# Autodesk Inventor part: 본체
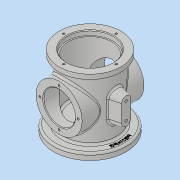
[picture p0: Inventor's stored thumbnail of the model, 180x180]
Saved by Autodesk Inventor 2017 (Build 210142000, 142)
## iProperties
Part Number: 본체
Material: 일반
Document SubType Name: Modeling
Designer: MRC
Density: 1 g/cm^3
Appearance: 기본값
Mass: 293.451 g
Surface Area: 769.493 cm^2
Volume: 293.451 cm^3
Author: MRC
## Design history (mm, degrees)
sketch "스케치1"
  geometry: C1 r 55 at (0, 0); 1 further point
  constraints: 1 centre point, 1 coincident
  dimensions: "d0" = 110 diameter of C1
extrude "돌출1" new body sketch "스케치1" distance "d1" = 10; taper "d2" = 0 deg
sketch "스케치2"
  geometry: C1 r 40 at (0, 0); 1 further point
  constraints: 1 centre point, 1 coincident
  dimensions: "d3" = 80 diameter of C1
extrude "돌출2" join sketch "스케치2" distance "d4" = 88; taper "d5" = 0 deg
sketch "스케치3"
  geometry: C1 r 47 at (0, 0); 1 further point
  constraints: 1 centre point, 1 coincident
  dimensions: "d6" = 94 diameter of C1
extrude "돌출3" join sketch "스케치3" distance "d7" = 10; taper "d8" = 0 deg
sketch "스케치4"
  geometry: L1 (-55, 0)-(55, 0) reference; C1 r 35 at (0, 54); 1 further point
  constraints: 1 centre point, 1 vertical alignment
  dimensions: "d9" = 70 diameter of C1; "d10" = 54 distance from line of L1 C1.centre
extrude "돌출4" join sketch "스케치4" stored distance "d11" = 94; taper "d12" = 0 deg
sketch "스케치5"
  geometry: C1 r 35 at (0, 0); 1 further point
  constraints: 1 centre point, 1 coincident
  dimensions: "d13" = 70 diameter of C1
extrude "돌출5" cut sketch "스케치5" distance "d14" = 7; taper "d15" = 0 deg
sketch "스케치6"
  geometry: C1 r 33 at (0, 0); 1 further point
  constraints: 1 centre point, 1 coincident
  dimensions: "d16" = 66 diameter of C1
extrude "돌출6" cut sketch "스케치6" distance "d17" = 79; taper "d18" = 0 deg
sketch "스케치7"
  geometry: C1 r 33 at (0, 0); 1 further point
  constraints: 1 centre point, 1 coincident
  dimensions: "d19" = 66 diameter of C1
extrude "돌출7" cut sketch "스케치7" distance "d20" = 16; taper "d21" = 0 deg
sketch "스케치8"
  geometry: C1 r 5 at (0, 0); 1 further point
  constraints: 1 centre point, 1 coincident
  dimensions: "d22" = 10 diameter of C1
extrude "돌출8" cut sketch "스케치8" distance "d23" = 16; taper "d24" = 0 deg
sketch "스케치9"
  geometry: C1 r 24 at (0, 0); 1 further point
  constraints: 1 centre point
  dimensions: "d25" = 48 diameter of C1
extrude "돌출9" cut sketch "스케치9" distance "d26" = 94; taper "d27" = 0 deg
sketch "스케치10"
  geometry: C1 r 24 at (0, 0) reference; C2 r 35 at (0, 0) reference; A1 r 29 centre (0, 0) between (0, 29) and (-29, 0); 3 further points
  constraints: 4 point on circle, 2 horizontal alignment, 2 vertical alignment, 1 centre point, 1 coincident
  dimensions: "d28" = 58 diameter of A1
hole "구멍1" sketch "스케치10" at (0, 29), (-29, 0), (29, 0), (0, -29) diameter "d29" = 3.242; stored, may be unused: countersink angle "d33" = 90 deg, drill point angle "d35" = 118 deg; dims "d30" = 6, "d31" = 4, "d32" = 2, "d34" = 8
sketch "스케치11"
  geometry: C1 r 35 at (0, 0) reference; C2 r 47 at (0, 0) reference; A1 r 40 centre (0, 0) between (0, 40) and (-40, 0); 3 further points
  constraints: 4 point on circle, 2 horizontal alignment, 2 vertical alignment, 1 centre point, 1 coincident
  dimensions: "d36" = 80 diameter of A1
hole "구멍2" sketch "스케치11" at (0, 40), (-40, 0), (0, -40), (40, 0) diameter "d37" = 3.242; stored, may be unused: countersink angle "d41" = 90 deg, drill point angle "d43" = 118 deg; dims "d38" = 6, "d39" = 4, "d40" = 2, "d42" = 8
node "작업 평면1"
sketch "스케치12"
  geometry: L1 (67, 0)-(41, 0); L2 (67, 7)-(41, 7); L3 (41, -7)-(67, -7); L4 (0, 55)-(0, -55) reference; A1 r 7 centre (67, 0) between (67, -7) and (67, 7); A2 r 7 centre (41, 0) between (41, 7) and (41, -7); 3 further points
  constraints: 8 end point, 4 point on circle, 4 tangent, 2 centre point, 2 midpoint, 1 horizontal, 1 horizontal alignment, 1 parallel
  dimensions: "d46" = 7 radius of A1; "d47" = 54 distance from line of point (54, 0) L4; "d50" = 40 dimension on A2 A1
extrude "돌출10" join sketch "스케치12" stored distance "d48" = 94; taper "d49" = 15 deg
sketch "스케치14"
  geometry: L1 (-7, 67)-(-7, 41) reference; L2 (7, 41)-(7, 67) reference; A1 r 7 centre (0, 41) between (-7, 41) and (7, 41) reference; A2 r 7 centre (0, 67) between (7, 67) and (-7, 67) reference; 3 further points
  constraints: 2 coincident
hole "구멍3" sketch "스케치14" at (0, 67), (0, 41) diameter "d51" = 4.134; stored, may be unused: countersink angle "d55" = 90 deg, drill point angle "d57" = 118 deg; dims "d52" = 6, "d53" = 4, "d54" = 2, "d56" = 8
chamfer "모따기1" distance "d58" = 1; stored, may be unused: second distance "d59" = 2, angle "d60" = 45 deg
fillet "모깎기1" dims "d61" = 3
fillet "모깎기2" dims "d62" = 3
sketch "스케치15"
  geometry: C1 r 50 at (0, 0); 1 further point
  constraints: 1 centre point, 1 coincident, 1 other
  dimensions: "d63" = 100 diameter of C1
feature "엠보싱1" sketch "스케치15" dims "d64" = 0.5, "d65" = 0
node "솔리드1"
mirror "미러1"
node "투영된 루프1"
node "투영된 루프2"
node "투영된 루프3"
other parameters: "d44" = 55
